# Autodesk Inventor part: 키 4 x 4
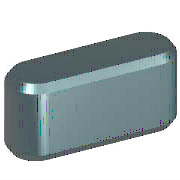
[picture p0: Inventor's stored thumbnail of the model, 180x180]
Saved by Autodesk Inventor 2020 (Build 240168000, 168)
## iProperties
IsCustomPart: 0
Created: 2009-02
Part Number: 키 4 x 4
Material: 강철, 연강
Description: 키 및 해당 키홈
Document SubType Name: Modeling
Standard: KS B 1311
Designer: KYOUNG IL JANG
Standards Organization: KS
Language: ko-KR
Size Designation: 4 x 4 x 12
Categories: <MemberInstance><Categories><Category DisplayName="샤프트 부품" InternalName="7f7aeb1f-a693-4053-b835-cee3144e0d98" Mnemonic="SHFT"><Category DisplayName="키" Interna
Density: 7.86 g/cm^3
Mass: 1.38739 g
Surface Area: 1.94869 cm^2
Volume: 0.176513 cm^3
Appearance: 노란색
Author: KYOUNG IL JANG
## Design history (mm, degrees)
workplane "Work Plane1"
workplane "Work Plane2"
sketch "스케치1"
  geometry: L1 (2, 2)-(10, 2); L2 (10, -2)-(2, -2); L3 (0, 9.4)-(0, -7.4) reference; L4 (-5, 0)-(30, 0) reference; L5 (12, 0)-(12, 7); A1 r 2 centre (2, 0) between (2, 2) and (2, -2); A2 r 2 centre (10, 0) between (10, -2) and (10, 2)
  constraints: 6 end point, 5 point on circle, 4 tangent, 3 point on line, 2 centre point, 1 horizontal, 1 parallel, 1 perpendicular
  dimensions: "d0" = 2 radius of A1 (= 0.5 x PB); "d13" = 2 radius of A2 (= 0.5 x PB); "d14" = 12 distance between parallel lines of L5 L3 (= NLG)
extrude "본체1" new body sketch "스케치1" taper "d3" = 0 deg; stored distance "d4" = 10
workplane "Work Plane3"
body "Solid1"
chamfer "모따기1" distance "d8" = 0.25 (= PHH); stored, may be unused: second distance "d9" = 0.25 (= PHH), angle "d15" = 45 deg
other parameters: "d1" = -2.5 (= -PNT), "d2" = 1.5 (= PH - PNT), "NLG" = 12 [user parameter; used in 3 equation terms], "PB" = 4 [user parameter; used in 2 equation terms], "PNT" = 2.5 [user parameter; used in 2 equation terms], "PH" = 4 [user parameter; used in 1 equation term], "PHH" = 0.25 [user parameter; used in 2 equation terms], "d10" = 0, "d16" = 0, "d17" = 0, "d18" = 0, "PLB2" = 12 (= NLG) [user parameter], "WDMAX" = 12 [user parameter], "PLB1" = 12 (= NLG) [user parameter], "RR" = 0.08 [user parameter], "PUEB" = 1.8 [user parameter]
